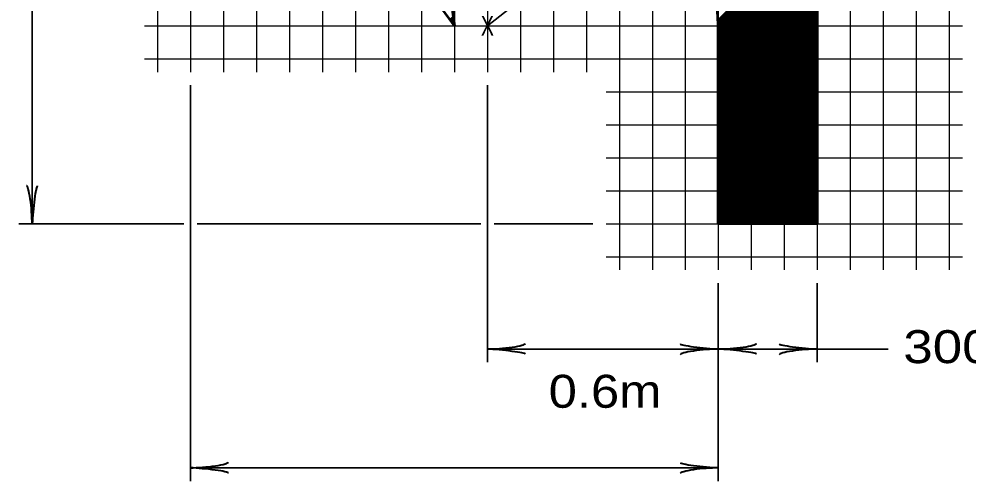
# Model space of a CAD drawing. Extents: x -96 to 617, y -65 to 388.
# Drawn here: x 111.1 to 183.1, y 226.1 to 261.1 of the extents above; entities that cross this region are included whole.
import ezdxf
from ezdxf.enums import TextEntityAlignment as Align

# ---------------------------------------------------------------- set-up
doc = ezdxf.new("R2010")
doc.units = 0
doc.layers.add('1', color=7, linetype='Continuous', lineweight=53)

msp = doc.modelspace()

# ---------------------------------------------------------------- linework, layer by layer
at = {"layer": '1', "lineweight": 25}
for p, q in [((161.579, 349.099), (161.579, 242.099)), ((164.079, 349.099), (164.079, 242.099)), ((166.579, 349.099), (166.579, 242.099)), ((169.079, 349.099), (169.079, 242.099)), ((171.579, 349.099), (171.579, 242.099)), ((174.079, 349.099), (174.079, 242.099)), ((176.579, 349.099), (176.579, 242.099)), ((179.079, 349.099), (179.079, 242.099)), ((181.579, 349.099), (181.579, 242.099)), ((121.579, 314.099), (121.579, 257.099)), ((124.079, 314.099), (124.079, 257.099)), ((126.579, 314.099), (126.579, 257.099)), ((129.079, 314.099), (129.079, 257.099)), ((131.579, 314.099), (131.579, 257.099)), ((134.079, 314.099), (134.079, 257.099)), ((136.579, 314.099), (136.579, 257.099)), ((139.079, 314.099), (139.079, 257.099)), ((141.579, 314.099), (141.579, 257.099)), ((144.079, 314.099), (144.079, 257.099)), ((156.579, 267.491), (156.579, 242.099)), ((146.579, 267.007), (146.579, 257.099)), ((154.079, 265.789), (154.079, 257.099)), ((151.579, 263.939), (151.579, 257.099)), ((149.079, 261.867), (149.079, 257.099)), ((120.579, 260.599), (146.579, 260.599)), ((120.579, 258.099), (182.579, 258.099)), ((155.579, 255.599), (182.579, 255.599)), ((155.579, 253.099), (182.579, 253.099)), ((155.579, 250.599), (182.579, 250.599)), ((155.579, 248.099), (182.579, 248.099)), ((155.579, 245.599), (182.579, 245.599)), ((155.579, 243.099), (182.579, 243.099))]:
    msp.add_line(p, q, dxfattribs=at)
at = {"layer": '1', "lineweight": 35}
for p, q in [((160.156, 271.312), (146.579, 260.599)), ((124.079, 256.099), (124.079, 226.099)), ((146.579, 256.099), (146.579, 235.099)), ((123.579, 245.599), (111.079, 245.599)), ((146.079, 245.599), (124.579, 245.599)), ((154.579, 245.599), (147.079, 245.599)), ((164.079, 241.099), (164.079, 226.099)), ((171.579, 241.099), (171.579, 235.099)), ((146.579, 236.099), (164.079, 236.099)), ((176.962, 236.099), (164.079, 236.099)), ((124.079, 227.099), (164.079, 227.099))]:
    msp.add_line(p, q, dxfattribs=at)
at = {"layer": '1'}
for p, q in [((164.059, 260.999), (171.579, 268.519)), ((164.067, 260.83), (171.579, 268.342)), ((164.076, 260.662), (171.579, 268.165)), ((164.079, 260.488), (171.579, 267.988)), ((164.079, 260.312), (171.579, 267.812)), ((164.079, 260.135), (171.579, 267.635)), ((164.079, 259.958), (171.579, 267.458)), ((164.079, 259.781), (171.579, 267.281)), ((164.079, 259.605), (171.579, 267.105)), ((164.079, 259.428), (171.579, 266.928)), ((164.079, 259.251), (171.579, 266.751)), ((164.079, 259.074), (171.579, 266.574)), ((164.079, 258.897), (171.579, 266.397)), ((164.079, 258.721), (171.579, 266.221)), ((164.079, 258.544), (171.579, 266.044)), ((164.079, 258.367), (171.579, 265.867)), ((164.079, 258.19), (171.579, 265.69)), ((164.079, 258.014), (171.579, 265.514)), ((164.079, 257.837), (171.579, 265.337)), ((164.079, 257.66), (171.579, 265.16)), ((164.079, 257.483), (171.579, 264.983)), ((164.079, 257.306), (171.579, 264.806)), ((164.079, 257.13), (171.579, 264.63)), ((164.079, 256.953), (171.579, 264.453)), ((164.079, 256.776), (171.579, 264.276)), ((164.079, 256.599), (171.579, 264.099)), ((164.079, 256.423), (171.579, 263.923)), ((164.079, 256.246), (171.579, 263.746)), ((164.079, 256.069), (171.579, 263.569)), ((164.079, 255.892), (171.579, 263.392)), ((164.079, 255.715), (171.579, 263.215)), ((164.079, 255.539), (171.579, 263.039)), ((164.079, 255.362), (171.579, 262.862)), ((164.079, 255.185), (171.579, 262.685)), ((164.079, 255.008), (171.579, 262.508)), ((164.079, 254.832), (171.579, 262.332)), ((164.079, 254.655), (171.579, 262.155)), ((164.079, 254.478), (171.579, 261.978)), ((164.079, 254.301), (171.579, 261.801)), ((164.079, 254.124), (171.579, 261.625)), ((164.079, 253.948), (171.579, 261.448)), ((143.763, 261.032), (143.985, 261.254)), ((143.838, 260.93), (144.007, 261.1)), ((143.912, 260.828), (144.029, 260.945)), ((143.986, 260.726), (144.051, 260.79)), ((164.079, 253.771), (171.579, 261.271)), ((164.079, 253.594), (171.579, 261.094)), ((164.079, 253.417), (171.579, 260.917)), ((164.079, 253.241), (171.579, 260.741)), ((144.061, 260.623), (144.073, 260.636)), ((164.079, 253.064), (171.579, 260.564)), ((164.079, 252.887), (171.579, 260.387)), ((164.079, 252.71), (171.579, 260.21)), ((164.079, 252.534), (171.579, 260.034)), ((164.079, 252.357), (171.579, 259.857)), ((164.079, 252.18), (171.579, 259.68)), ((164.079, 252.003), (171.579, 259.503)), ((164.079, 251.826), (171.579, 259.326)), ((164.079, 251.65), (171.579, 259.15)), ((164.079, 251.473), (171.579, 258.973)), ((164.079, 251.296), (171.579, 258.796)), ((164.079, 251.119), (171.579, 258.619)), ((164.079, 250.942), (171.579, 258.442)), ((164.079, 250.766), (171.579, 258.266)), ((164.079, 250.589), (171.579, 258.089)), ((164.079, 250.412), (171.579, 257.912)), ((164.079, 250.235), (171.579, 257.735)), ((164.079, 250.059), (171.579, 257.559)), ((164.079, 249.882), (171.579, 257.382)), ((164.079, 249.705), (171.579, 257.205)), ((164.079, 249.528), (171.579, 257.028)), ((164.079, 249.352), (171.579, 256.852)), ((164.079, 249.175), (171.579, 256.675)), ((164.079, 248.998), (171.579, 256.498)), ((164.079, 248.821), (171.579, 256.321)), ((164.079, 248.644), (171.579, 256.144)), ((164.079, 248.468), (171.579, 255.968)), ((164.079, 248.291), (171.579, 255.791)), ((164.079, 248.114), (171.579, 255.614)), ((164.079, 247.937), (171.579, 255.437)), ((164.079, 247.761), (171.579, 255.261)), ((164.079, 247.584), (171.579, 255.084)), ((164.079, 247.407), (171.579, 254.907)), ((164.079, 247.23), (171.579, 254.73)), ((164.079, 247.053), (171.579, 254.553)), ((164.079, 246.877), (171.579, 254.377)), ((164.079, 246.7), (171.579, 254.2)), ((164.079, 246.523), (171.579, 254.023)), ((164.079, 246.346), (171.579, 253.846)), ((164.079, 246.17), (171.579, 253.67)), ((164.079, 245.993), (171.579, 253.493)), ((164.079, 245.816), (171.579, 253.316)), ((164.079, 245.639), (171.579, 253.139)), ((164.215, 245.599), (171.579, 252.963)), ((164.392, 245.599), (171.579, 252.786)), ((164.568, 245.599), (171.579, 252.609)), ((164.745, 245.599), (171.579, 252.432)), ((164.922, 245.599), (171.579, 252.255)), ((165.099, 245.599), (171.579, 252.079)), ((165.275, 245.599), (171.579, 251.902)), ((165.452, 245.599), (171.579, 251.725)), ((165.629, 245.599), (171.579, 251.548)), ((165.806, 245.599), (171.579, 251.371)), ((165.982, 245.599), (171.579, 251.195)), ((166.159, 245.599), (171.579, 251.018)), ((166.336, 245.599), (171.579, 250.841)), ((166.513, 245.599), (171.579, 250.664)), ((166.69, 245.599), (171.579, 250.488)), ((166.866, 245.599), (171.579, 250.311)), ((167.043, 245.599), (171.579, 250.134)), ((167.22, 245.599), (171.579, 249.957)), ((167.397, 245.599), (171.579, 249.78)), ((167.573, 245.599), (171.579, 249.604)), ((167.75, 245.599), (171.579, 249.427)), ((167.927, 245.599), (171.579, 249.25)), ((168.104, 245.599), (171.579, 249.073)), ((168.281, 245.599), (171.579, 248.897)), ((168.457, 245.599), (171.579, 248.72)), ((168.634, 245.599), (171.579, 248.543)), ((168.811, 245.599), (171.579, 248.366)), ((168.988, 245.599), (171.579, 248.189)), ((169.164, 245.599), (171.579, 248.013)), ((169.341, 245.599), (171.579, 247.836)), ((169.518, 245.599), (171.579, 247.659)), ((169.695, 245.599), (171.579, 247.482)), ((169.872, 245.599), (171.579, 247.306)), ((170.048, 245.599), (171.579, 247.129)), ((170.225, 245.599), (171.579, 246.952)), ((170.402, 245.599), (171.579, 246.775)), ((170.579, 245.599), (171.579, 246.599)), ((170.755, 245.599), (171.579, 246.422)), ((170.932, 245.599), (171.579, 246.245)), ((171.109, 245.599), (171.579, 246.068)), ((171.286, 245.599), (171.579, 245.891)), ((171.463, 245.599), (171.579, 245.715))]:
    msp.add_line(p, q, dxfattribs=at)
at = {"layer": '1', "lineweight": 25}
for points in [[(159.079, 349.099), (159.079, 266.604), (159.079, 242.099)], [(146.579, 260.599), (147.547, 260.599), (182.579, 260.599)]]:
    msp.add_lwpolyline(points, dxfattribs=at)
at = {"layer": '1', "lineweight": 35}
msp.add_lwpolyline([(112.079, 345.599), (112.079, 288.099), (112.079, 245.599)], dxfattribs=at)
at = {"layer": '1'}
for points in [[(155.329, 305.599), (167.829, 345.599), (180.329, 305.599), (171.579, 313.099), (171.579, 245.599), (164.079, 245.599), (164.079, 260.599)], [(149.079, 278.099), (141.579, 278.099), (144.079, 260.599), (124.079, 288.099), (146.579, 308.099), (141.579, 290.599)]]:
    msp.add_lwpolyline(points, dxfattribs=at)
msp.add_arc((145.536, 259.884), 18.556, 2.2078, 73.82193, dxfattribs=at)
at = {"layer": '1', "lineweight": 40}
for centre, major_axis, ratio, start_param, end_param in [((111.802, 246.69), (0.156, -1.786), 0.122415, 0.896353, 3.141593), ((111.802, 246.69), (0.156, -1.786), 0.122415, 0.896353, 3.141593), ((112.29, 246.719), (-0.176, -1.756), 0.07063, 3.140715, 5.41811), ((112.29, 246.719), (-0.176, -1.756), 0.07063, 3.140715, 5.41811), ((147.67, 236.375), (-1.786, -0.156), 0.122415, 0.896353, 3.141593), ((147.67, 236.375), (-1.786, -0.156), 0.122415, 0.896353, 3.141593), ((162.958, 236.31), (1.756, -0.176), 0.07063, 3.140715, 5.41811), ((162.958, 236.31), (1.756, -0.176), 0.07063, 3.140715, 5.41811), ((165.17, 236.375), (-1.786, -0.156), 0.122415, 0.896353, 3.141593), ((165.17, 236.375), (-1.786, -0.156), 0.122415, 0.896353, 3.141593), ((170.458, 236.31), (1.756, -0.176), 0.07063, 3.140715, 5.41811), ((170.458, 236.31), (1.756, -0.176), 0.07063, 3.140715, 5.41811), ((147.699, 235.887), (-1.756, 0.176), 0.07063, 3.140715, 5.41811), ((147.699, 235.887), (-1.756, 0.176), 0.07063, 3.140715, 5.41811), ((162.987, 235.822), (1.786, 0.156), 0.122415, 0.896353, 3.141593), ((162.987, 235.822), (1.786, 0.156), 0.122415, 0.896353, 3.141593), ((165.199, 235.887), (-1.756, 0.176), 0.07063, 3.140715, 5.41811), ((165.199, 235.887), (-1.756, 0.176), 0.07063, 3.140715, 5.41811), ((170.487, 235.822), (1.786, 0.156), 0.122415, 0.896353, 3.141593), ((170.487, 235.822), (1.786, 0.156), 0.122415, 0.896353, 3.141593), ((125.17, 227.375), (-1.786, -0.156), 0.122415, 0.896353, 3.141593), ((125.17, 227.375), (-1.786, -0.156), 0.122415, 0.896353, 3.141593), ((125.199, 226.887), (-1.756, 0.176), 0.07063, 3.140715, 5.41811), ((125.199, 226.887), (-1.756, 0.176), 0.07063, 3.140715, 5.41811), ((162.987, 226.822), (1.786, 0.156), 0.122415, 0.896353, 3.141593), ((162.987, 226.822), (1.786, 0.156), 0.122415, 0.896353, 3.141593), ((162.987, 226.822), (1.786, 0.156), 0.122415, 0.896353, 3.141593), ((162.958, 227.31), (1.756, -0.176), 0.07063, 3.140715, 5.41811), ((162.958, 227.31), (1.756, -0.176), 0.07063, 3.140715, 5.41811), ((162.958, 227.31), (1.756, -0.176), 0.07063, 3.140715, 5.41811)]:
    msp.add_ellipse(centre, major_axis=major_axis, ratio=ratio, start_param=start_param, end_param=end_param, dxfattribs=at)

# ---------------------------------------------------------------- texts
at = {"layer": '1'}
for s, height, width, p in [('X', 1.5, 0.75, (146.579, 259.849)), ('300mm', 2.5, 1.2, (184.788, 235.031)), ('0.6m', 2.5, 1.15, (155.496, 231.65))]:
    msp.add_text(s, height=height, dxfattribs=dict(at, width=width)).set_placement(p, align=Align.CENTER)

doc.saveas('drawing.dxf')
